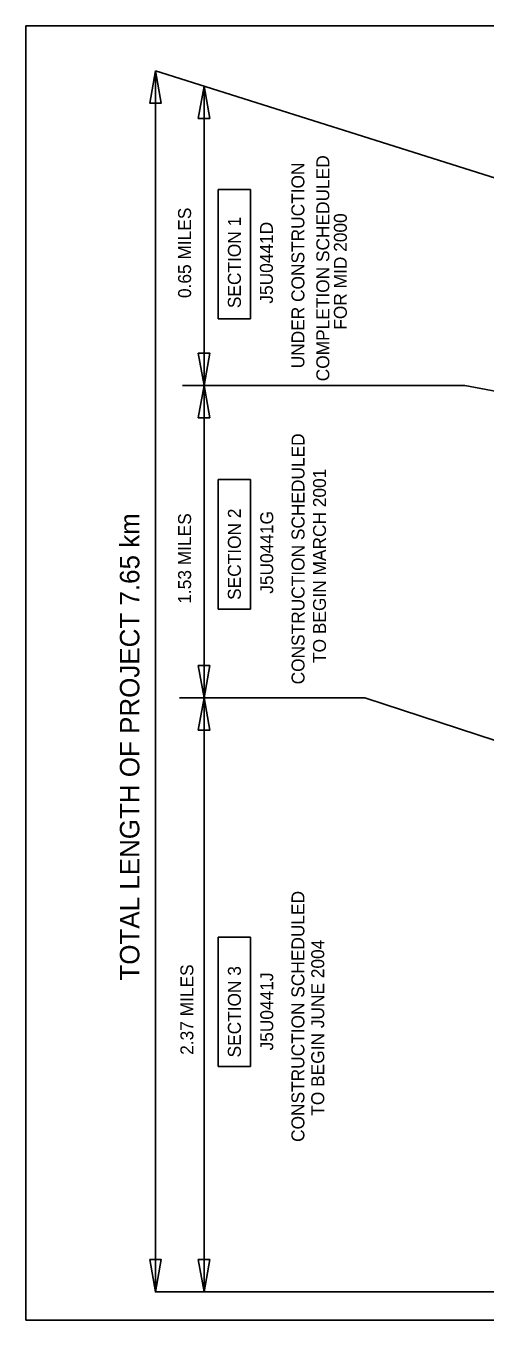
# Model space of a CAD drawing. Extents: x 5.01 to 9.58, y 0.27 to 3.39.
# Drawn here: x 5.014 to 6.043, y 0.321 to 3.219 of the extents above; entities that cross this region are included whole.
import ezdxf

# ---------------------------------------------------------------- set-up
doc = ezdxf.new("R2010")
doc.units = 0
doc.layers.add('Level 7', color=7, linetype='Continuous')
doc.layers.add('MO_001_VIEW_99', color=7, linetype='Continuous')

msp = doc.modelspace()

# ---------------------------------------------------------------- linework, layer by layer
at = {"layer": 'Level 7'}
for p, q in [((5.2916, 3.0465), (5.3044, 3.119)), ((5.3044, 3.119), (5.3044, 0.3838)), ((5.3044, 3.119), (6.9335, 2.6046)), ((5.3044, 3.119), (5.3173, 3.0465)), ((5.4003, 3.0121), (5.4131, 3.0846)), ((5.4131, 3.0846), (5.426, 3.0121)), ((5.4131, 3.0846), (5.4131, 0.3838)), ((5.4449, 2.853), (5.5174, 2.853)), ((5.4449, 2.853), (5.4449, 2.5631)), ((5.5174, 2.853), (5.5174, 2.5631)), ((5.4449, 2.5631), (5.5174, 2.5631)), ((5.4003, 2.4867), (5.4131, 2.4143)), ((5.4131, 2.4143), (5.426, 2.4867)), ((5.3651, 2.4143), (5.9971, 2.4143)), ((5.4003, 2.3418), (5.4131, 2.4143)), ((5.4131, 2.4143), (5.426, 2.3418)), ((5.9971, 2.4143), (7.0472, 2.2101)), ((5.4449, 2.2031), (5.5174, 2.2031)), ((5.4449, 2.2031), (5.4449, 1.9132)), ((5.5174, 2.2031), (5.5174, 1.9132)), ((5.4449, 1.9132), (5.5174, 1.9132)), ((5.4003, 1.7867), (5.4131, 1.7142)), ((5.4131, 1.7142), (5.426, 1.7867)), ((5.3579, 1.7142), (5.7734, 1.7142)), ((5.4003, 1.6418), (5.4131, 1.7142)), ((5.4131, 1.7142), (5.426, 1.6418)), ((5.7734, 1.7142), (7.1715, 1.2576)), ((5.4449, 1.1782), (5.5174, 1.1782)), ((5.4449, 1.1782), (5.4449, 0.8883)), ((5.5174, 1.1782), (5.5174, 0.8883)), ((5.4449, 0.8883), (5.5174, 0.8883)), ((5.2916, 0.4563), (5.3173, 0.4563)), ((5.2916, 0.4563), (5.3044, 0.3838)), ((5.3044, 0.3838), (5.3173, 0.4563)), ((5.4003, 0.4563), (5.426, 0.4563)), ((5.4003, 0.4563), (5.4131, 0.3838)), ((5.4131, 0.3838), (5.426, 0.4563)), ((5.3044, 0.3838), (8.2666, 0.3838))]:
    msp.add_line(p, q, dxfattribs=at)
for points in [[(5.3044, 3.119), (5.2916, 3.0465), (5.3173, 3.0465)], [(5.4131, 3.0846), (5.4003, 3.0121), (5.426, 3.0121)], [(5.4003, 2.4867), (5.4131, 2.4143), (5.426, 2.4867)], [(5.4003, 2.3418), (5.426, 2.3418), (5.4131, 2.4143)], [(5.4003, 1.7867), (5.4131, 1.7142), (5.426, 1.7867)], [(5.4003, 1.6418), (5.426, 1.6418), (5.4131, 1.7142)], [(5.2916, 0.4563), (5.3044, 0.3838), (5.3173, 0.4563)], [(5.4003, 0.4563), (5.4131, 0.3838), (5.426, 0.4563)]]:
    msp.add_lwpolyline(points, close=True, dxfattribs=at)
at = {"layer": 'MO_001_VIEW_99'}
for p, q in [((5.014, 3.2194), (5.014, 0.3206)), ((5.014, 3.2194), (9.5796, 3.2194)), ((5.014, 0.3206), (9.5796, 0.3206))]:
    msp.add_line(p, q, dxfattribs=at)

# ---------------------------------------------------------------- texts
at = {"layer": 'Level 7'}
for s, height, p in [('UNDER CONSTRUCTION', 0.028993, (5.6379, 2.4524)), ('COMPLETION SCHEDULED', 0.028992, (5.6937, 2.4234)), ('0.65 MILES', 0.02899, (5.3841, 2.6098)), ('SECTION 1', 0.02899, (5.4956, 2.5872)), ('FOR MID 2000', 0.028993, (5.733, 2.5389)), ('J5U0441D', 0.02899, (5.5674, 2.5973)), ('CONSTRUCTION SCHEDULED', 0.028992, (5.6382, 1.7445)), ('TO BEGIN MARCH 2001', 0.028993, (5.6863, 1.7924)), ('TOTAL LENGTH OF PROJECT 7.65 km', 0.043482, (5.2682, 1.0811)), ('1.53 MILES', 0.02899, (5.3841, 1.9252)), ('SECTION 2', 0.02899, (5.4956, 1.9337)), ('J5U0441G', 0.02899, (5.5681, 1.9475)), ('CONSTRUCTION SCHEDULED', 0.028993, (5.6379, 0.7197)), ('TO BEGIN JUNE 2004', 0.028993, (5.6823, 0.7784)), ('2.37 MILES', 0.02899, (5.3892, 0.9148)), ('SECTION 3', 0.02899, (5.4956, 0.9089)), ('J5U0441J', 0.02899, (5.5681, 0.9246))]:
    msp.add_text(s, height=height, rotation=90, dxfattribs=at).set_placement(p)

doc.saveas('drawing.dxf')
